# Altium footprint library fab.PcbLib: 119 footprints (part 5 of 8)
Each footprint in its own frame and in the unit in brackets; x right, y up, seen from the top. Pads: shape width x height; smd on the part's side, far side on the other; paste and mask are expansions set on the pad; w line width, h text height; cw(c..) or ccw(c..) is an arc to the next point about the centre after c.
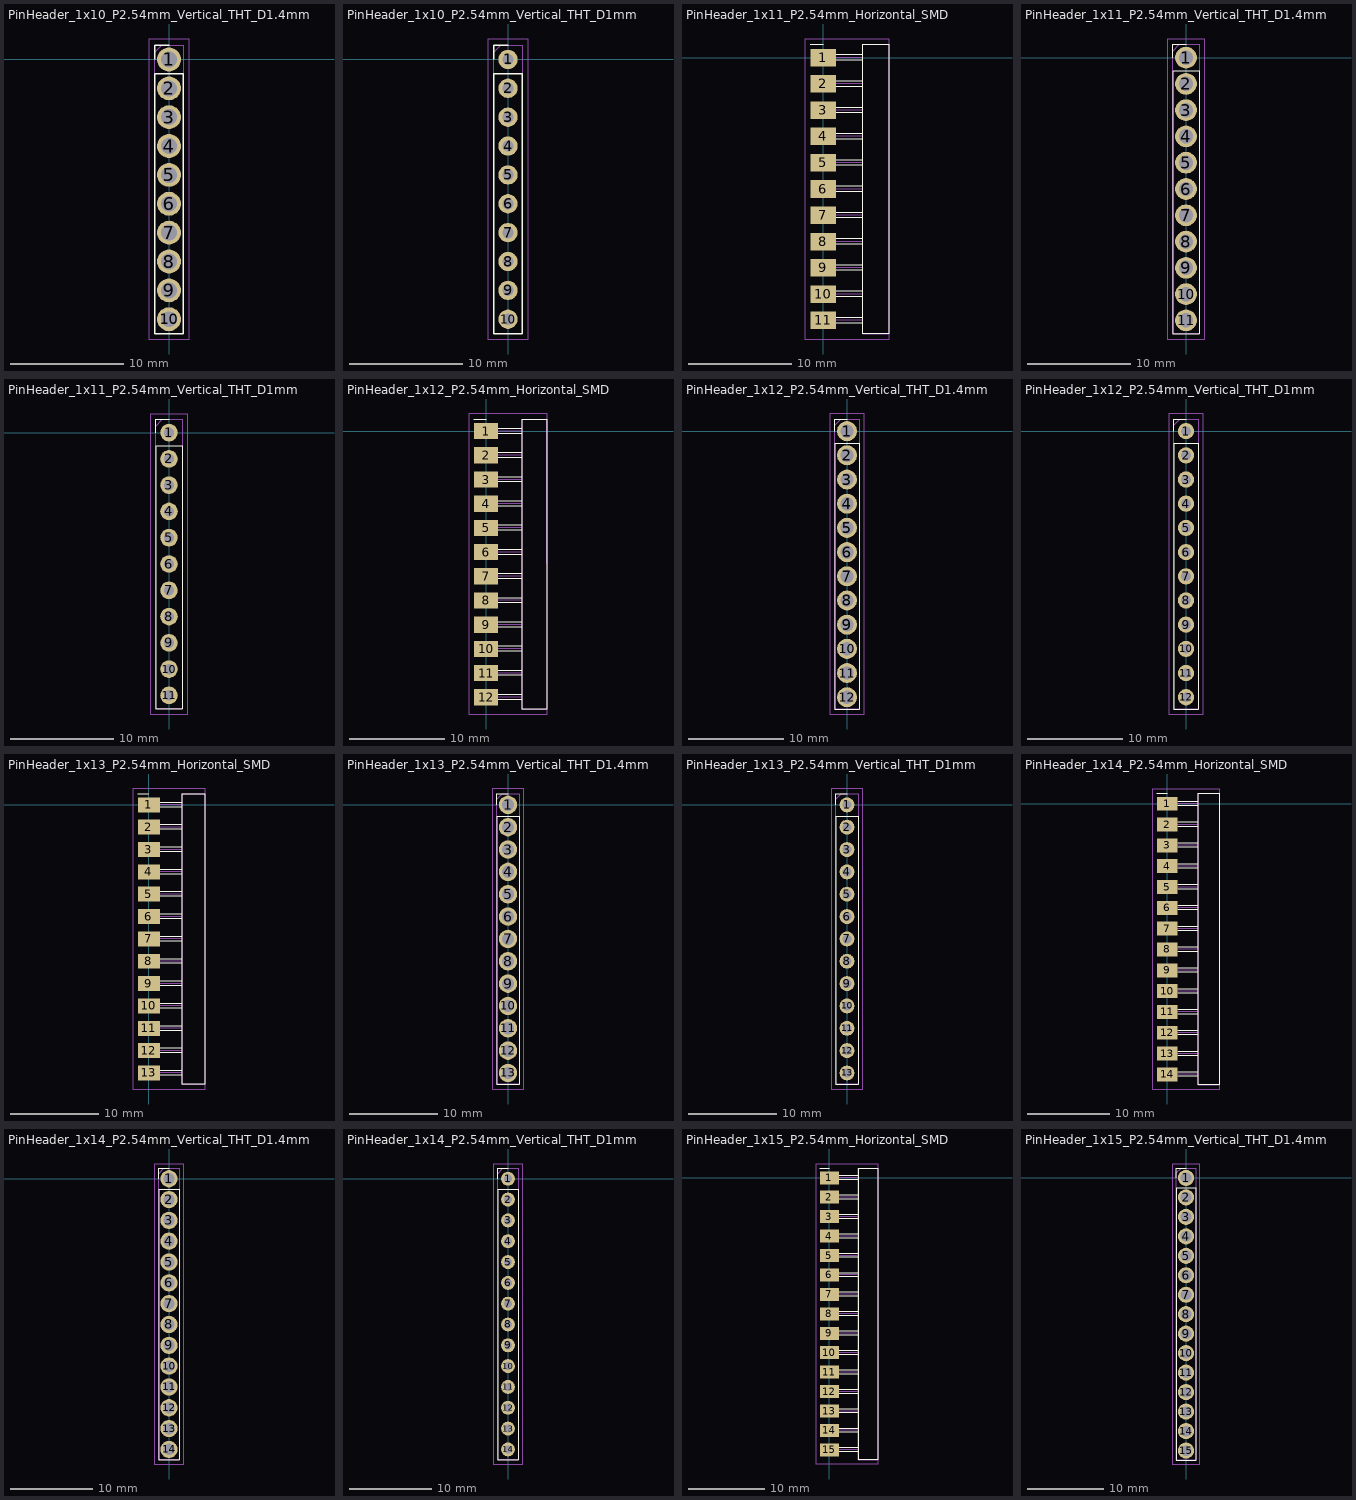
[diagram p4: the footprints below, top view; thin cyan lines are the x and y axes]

## PinHeader_1x10_P2.54mm_Vertical_THT_D1.4mm [mm]
pads (10):
  round 2.1 hole 1.4: 1(0,0) 2(0,-2.54) 3(0,-5.08) 4(0,-7.62) 5(0,-10.16) 6(0,-12.7) 7(0,-15.24) 8(0,-17.78) 9(0,-20.32) 10(0,-22.86)
F.SilkS:
  lines w0.12: -1.27,0 -1.27,1.27 0,1.27 ; -1.27,-24.13 -1.27,-1.27 1.27,-1.27 1.27,-24.13 -1.27,-24.13
F.CrtYd:
  lines w0.05: -1.8,-24.6 1.8,-24.6 1.8,1.8 -1.8,1.8 -1.8,-24.6
F.Fab:
  lines w0.1: -1.27,-24.13 -1.27,0.635 -0.635,1.27 1.27,1.27 1.27,-24.13 -1.27,-24.13
  text "%R" at 0.294,-9.283 h1

## PinHeader_1x10_P2.54mm_Vertical_THT_D1mm [mm]
pads (10):
  round 1.7 hole 1: 1(0,0)
  rrect100% 1.7x1.7 hole 1: 2(0,-2.54) 3(0,-5.08) 4(0,-7.62) 5(0,-10.16) 6(0,-12.7) 7(0,-15.24) 8(0,-17.78) 9(0,-20.32) 10(0,-22.86)
F.SilkS:
  lines w0.12: -1.27,0 -1.27,1.27 0,1.27 ; -1.27,-24.13 1.27,-24.13 1.27,-1.27 -1.27,-1.27 -1.27,-24.13
F.CrtYd:
  lines w0.05: -1.8,-24.6 -1.8,1.8 1.8,1.8 1.8,-24.6 -1.8,-24.6
F.Fab:
  lines w0.1: -1.27,-24.13 1.27,-24.13 1.27,1.27 -0.635,1.27 -1.27,0.635 -1.27,-24.13
  text "%R" at 0.294,-9.283 h1

## PinHeader_1x11_P2.54mm_Horizontal_SMD [mm]
pads (11):
  rect 2.5x1.7 smd: 1(0,0) 2(0,-2.54) 3(0,-5.08) 4(0,-7.62) 5(0,-10.16) 6(0,-12.7) 7(0,-15.24) 8(0,-17.78) 9(0,-20.32) 10(0,-22.86) 11(0,-25.4)
F.SilkS:
  lines w0.12: -1.27,1.27 0,1.27 ; 1.27,-25.654 3.81,-25.654 ; 1.27,-25.146 3.81,-25.146 ; 1.27,-23.114 3.81,-23.114 ; 1.27,-22.606 3.81,-22.606 ; 1.27,-20.574 3.81,-20.574 ; 1.27,-20.066 3.81,-20.066 ; 1.27,-18.034 3.81,-18.034 ; 1.27,-17.526 3.81,-17.526 ; 1.27,-15.494 3.81,-15.494 ; 1.27,-14.986 3.81,-14.986 ; 1.27,-12.954 3.81,-12.954 ; 1.27,-12.446 3.81,-12.446 ; 1.27,-10.414 3.81,-10.414 ; 1.27,-9.906 3.81,-9.906 ; 1.27,-7.874 3.81,-7.874 ; 1.27,-7.366 3.81,-7.366 ; 1.27,-5.334 3.81,-5.334 ; 1.27,-4.826 3.81,-4.826 ; 1.27,-2.794 3.81,-2.794 ; 1.27,-2.286 3.81,-2.286 ; 1.27,-0.254 3.81,-0.254 ; 1.27,0.254 3.81,0.254 ; 3.81,-26.67 3.81,1.27 6.35,1.27 6.35,-26.67 3.81,-26.67
F.CrtYd:
  lines w0.05: -1.8,-27.2 -1.8,1.8 6.4,1.8 6.4,-27.2 -1.8,-27.2
F.Fab:
  lines w0.1: -0.635,-25.4 3.81,-25.4 ; -0.635,-23.114 -0.635,-22.606 ; -0.635,-22.86 3.81,-22.86 ; -0.635,-20.574 -0.635,-20.066 ; -0.635,-20.32 3.81,-20.32 ; -0.635,-18.034 -0.635,-17.526 ; -0.635,-17.78 3.81,-17.78 ; -0.635,-15.494 -0.635,-14.986 ; -0.635,-15.24 3.81,-15.24 ; -0.635,-12.954 -0.635,-12.446 ; -0.635,-12.7 3.81,-12.7 ; -0.635,-10.414 -0.635,-9.906 ; -0.635,-10.16 3.81,-10.16 ; -0.635,-7.874 -0.635,-7.366 ; -0.635,-7.62 3.81,-7.62 ; -0.635,-5.334 -0.635,-4.826 ; -0.635,-5.08 3.81,-5.08 ; -0.635,-2.794 -0.635,-2.286 ; -0.635,-2.54 3.81,-2.54 ; -0.635,-0.254 -0.635,0.254 ; -0.635,0 3.81,0 ; 3.8,-26.67 6.35,-26.67 6.34,1.27 3.8,1.27 3.8,-26.67
  text "%R" at 2.834,-13.093 h1

## PinHeader_1x11_P2.54mm_Vertical_THT_D1.4mm [mm]
pads (11):
  round 2.1 hole 1.4: 1(0,0) 2(0,-2.54) 3(0,-5.08) 4(0,-7.62) 5(0,-10.16) 6(0,-12.7) 7(0,-15.24) 8(0,-17.78) 9(0,-20.32) 10(0,-22.86) 11(0,-25.4)
F.SilkS:
  lines w0.12: -1.27,0 -1.27,1.27 0,1.27 ; -1.27,-26.67 1.27,-26.67 1.27,-1.27 -1.27,-1.27 -1.27,-26.67
F.CrtYd:
  lines w0.05: -1.8,-27.2 -1.8,1.8 1.8,1.8 1.8,-27.2 -1.8,-27.2
F.Fab:
  lines w0.1: -1.27,-26.67 1.27,-26.67 1.27,1.27 -0.635,1.27 -1.27,0.635 -1.27,-26.67
  text "%R" at 0.294,-9.283 h1

## PinHeader_1x11_P2.54mm_Vertical_THT_D1mm [mm]
pads (11):
  round 1.7 hole 1: 1(0,0)
  rrect100% 1.7x1.7 hole 1: 2(0,-2.54) 3(0,-5.08) 4(0,-7.62) 5(0,-10.16) 6(0,-12.7) 7(0,-15.24) 8(0,-17.78) 9(0,-20.32) 10(0,-22.86) 11(0,-25.4)
F.SilkS:
  lines w0.12: -1.27,0 -1.27,1.27 0,1.27 ; -1.27,-26.67 -1.27,-1.27 1.27,-1.27 1.27,-26.67 -1.27,-26.67
F.CrtYd:
  lines w0.05: -1.8,-27.2 1.8,-27.2 1.8,1.8 -1.8,1.8 -1.8,-27.2
F.Fab:
  lines w0.1: -1.27,-26.67 -1.27,0.635 -0.635,1.27 1.27,1.27 1.27,-26.67 -1.27,-26.67
  text "%R" at 0.294,-9.283 h1

## PinHeader_1x12_P2.54mm_Horizontal_SMD [mm]
pads (12):
  rect 2.5x1.7 smd: 1(0,0) 2(0,-2.54) 3(0,-5.08) 4(0,-7.62) 5(0,-10.16) 6(0,-12.7) 7(0,-15.24) 8(0,-17.78) 9(0,-20.32) 10(0,-22.86) 11(0,-25.4) 12(0,-27.94)
F.SilkS:
  lines w0.12: -1.27,1.27 0,1.27 ; 1.27,-28.194 3.81,-28.194 ; 1.27,-27.686 3.81,-27.686 ; 1.27,-25.654 3.81,-25.654 ; 1.27,-25.146 3.81,-25.146 ; 1.27,-23.114 3.81,-23.114 ; 1.27,-22.606 3.81,-22.606 ; 1.27,-20.574 3.81,-20.574 ; 1.27,-20.066 3.81,-20.066 ; 1.27,-18.034 3.81,-18.034 ; 1.27,-17.526 3.81,-17.526 ; 1.27,-15.494 3.81,-15.494 ; 1.27,-14.986 3.81,-14.986 ; 1.27,-12.954 3.81,-12.954 ; 1.27,-12.446 3.81,-12.446 ; 1.27,-10.414 3.81,-10.414 ; 1.27,-9.906 3.81,-9.906 ; 1.27,-7.874 3.81,-7.874 ; 1.27,-7.366 3.81,-7.366 ; 1.27,-5.334 3.81,-5.334 ; 1.27,-4.826 3.81,-4.826 ; 1.27,-2.794 3.81,-2.794 ; 1.27,-2.286 3.81,-2.286 ; 1.27,-0.254 3.81,-0.254 ; 1.27,0.254 3.81,0.254 ; 3.81,-29.21 6.35,-29.21 6.35,1.27 3.81,1.27 3.81,-29.21
F.CrtYd:
  lines w0.05: -1.8,-29.7 6.4,-29.7 6.4,1.8 -1.8,1.8 -1.8,-29.7
F.Fab:
  lines w0.1: -0.635,-27.94 3.81,-27.94 ; -0.635,-25.4 3.81,-25.4 ; -0.635,-23.114 -0.635,-22.606 ; -0.635,-22.86 3.81,-22.86 ; -0.635,-20.574 -0.635,-20.066 ; -0.635,-20.32 3.81,-20.32 ; -0.635,-18.034 -0.635,-17.526 ; -0.635,-17.78 3.81,-17.78 ; -0.635,-15.494 -0.635,-14.986 ; -0.635,-15.24 3.81,-15.24 ; -0.635,-12.954 -0.635,-12.446 ; -0.635,-12.7 3.81,-12.7 ; -0.635,-10.414 -0.635,-9.906 ; -0.635,-10.16 3.81,-10.16 ; -0.635,-7.874 -0.635,-7.366 ; -0.635,-7.62 3.81,-7.62 ; -0.635,-5.334 -0.635,-4.826 ; -0.635,-5.08 3.81,-5.08 ; -0.635,-2.794 -0.635,-2.286 ; -0.635,-2.54 3.81,-2.54 ; -0.635,-0.254 -0.635,0.254 ; -0.635,0 3.81,0 ; 3.8,-29.21 6.35,-29.21 6.34,1.27 3.8,1.27 3.81,-29.21
  text "%R" at 2.834,-14.363 h1

## PinHeader_1x12_P2.54mm_Vertical_THT_D1.4mm [mm]
pads (12):
  round 2.1 hole 1.4: 1(0,0) 2(0,-2.54) 3(0,-5.08) 4(0,-7.62) 5(0,-10.16) 6(0,-12.7) 7(0,-15.24) 8(0,-17.78) 9(0,-20.32) 10(0,-22.86) 11(0,-25.4) 12(0,-27.94)
F.SilkS:
  lines w0.12: -1.27,0 -1.27,1.27 0,1.27 ; -1.27,-29.21 1.27,-29.21 1.27,-1.27 -1.27,-1.27 -1.27,-29.21
F.CrtYd:
  lines w0.05: -1.8,-29.7 -1.8,1.8 1.8,1.8 1.8,-29.7 -1.8,-29.7
F.Fab:
  lines w0.1: -1.27,-29.21 1.27,-29.21 1.27,1.27 -0.635,1.27 -1.27,0.635 -1.27,-29.21
  text "%R" at 0.294,-9.283 h1

## PinHeader_1x12_P2.54mm_Vertical_THT_D1mm [mm]
pads (12):
  round 1.7 hole 1: 1(0,0)
  rrect100% 1.7x1.7 hole 1: 2(0,-2.54) 3(0,-5.08) 4(0,-7.62) 5(0,-10.16) 6(0,-12.7) 7(0,-15.24) 8(0,-17.78) 9(0,-20.32) 10(0,-22.86) 11(0,-25.4) 12(0,-27.94)
F.SilkS:
  lines w0.12: -1.27,0 -1.27,1.27 0,1.27 ; -1.27,-29.21 -1.27,-1.27 1.27,-1.27 1.27,-29.21 -1.27,-29.21
F.CrtYd:
  lines w0.05: -1.8,-29.7 1.8,-29.7 1.8,1.8 -1.8,1.8 -1.8,-29.7
F.Fab:
  lines w0.1: -1.27,-29.21 -1.27,0.635 -0.635,1.27 1.27,1.27 1.27,-29.21 -1.27,-29.21
  text "%R" at 0.294,-9.283 h1

## PinHeader_1x13_P2.54mm_Horizontal_SMD [mm]
pads (13):
  rect 2.5x1.7 smd: 1(0,0) 2(0,-2.54) 3(0,-5.08) 4(0,-7.62) 5(0,-10.16) 6(0,-12.7) 7(0,-15.24) 8(0,-17.78) 9(0,-20.32) 10(0,-22.86) 11(0,-25.4) 12(0,-27.94) 13(0,-30.48)
F.SilkS:
  lines w0.12: -1.27,1.27 0,1.27 ; 1.27,-30.734 3.81,-30.734 ; 1.27,-30.226 3.81,-30.226 ; 1.27,-28.194 3.81,-28.194 ; 1.27,-27.686 3.81,-27.686 ; 1.27,-25.654 3.81,-25.654 ; 1.27,-25.146 3.81,-25.146 ; 1.27,-23.114 3.81,-23.114 ; 1.27,-22.606 3.81,-22.606 ; 1.27,-20.574 3.81,-20.574 ; 1.27,-20.066 3.81,-20.066 ; 1.27,-18.034 3.81,-18.034 ; 1.27,-17.526 3.81,-17.526 ; 1.27,-15.494 3.81,-15.494 ; 1.27,-14.986 3.81,-14.986 ; 1.27,-12.954 3.81,-12.954 ; 1.27,-12.446 3.81,-12.446 ; 1.27,-10.414 3.81,-10.414 ; 1.27,-9.906 3.81,-9.906 ; 1.27,-7.874 3.81,-7.874 ; 1.27,-7.366 3.81,-7.366 ; 1.27,-5.334 3.81,-5.334 ; 1.27,-4.826 3.81,-4.826 ; 1.27,-2.794 3.81,-2.794 ; 1.27,-2.286 3.81,-2.286 ; 1.27,-0.254 3.81,-0.254 ; 1.27,0.254 3.81,0.254 ; 3.81,-31.75 3.81,1.27 6.35,1.27 6.35,-31.75 3.81,-31.75
F.CrtYd:
  lines w0.05: -1.8,-32.3 -1.8,1.8 6.4,1.8 6.4,-32.3 -1.8,-32.3
F.Fab:
  lines w0.1: -0.635,-30.48 3.81,-30.48 ; -0.635,-27.94 3.81,-27.94 ; -0.635,-25.4 3.81,-25.4 ; -0.635,-23.114 -0.635,-22.606 ; -0.635,-22.86 3.81,-22.86 ; -0.635,-20.574 -0.635,-20.066 ; -0.635,-20.32 3.81,-20.32 ; -0.635,-18.034 -0.635,-17.526 ; -0.635,-17.78 3.81,-17.78 ; -0.635,-15.494 -0.635,-14.986 ; -0.635,-15.24 3.81,-15.24 ; -0.635,-12.954 -0.635,-12.446 ; -0.635,-12.7 3.81,-12.7 ; -0.635,-10.414 -0.635,-9.906 ; -0.635,-10.16 3.81,-10.16 ; -0.635,-7.874 -0.635,-7.366 ; -0.635,-7.62 3.81,-7.62 ; -0.635,-5.334 -0.635,-4.826 ; -0.635,-5.08 3.81,-5.08 ; -0.635,-2.794 -0.635,-2.286 ; -0.635,-2.54 3.81,-2.54 ; -0.635,-0.254 -0.635,0.254 ; -0.635,0 3.81,0 ; 3.8,-31.75 6.35,-31.75 6.34,1.27 3.8,1.27 3.8,-31.75
  text "%R" at 2.834,-15.633 h1

## PinHeader_1x13_P2.54mm_Vertical_THT_D1.4mm [mm]
pads (13):
  round 2.1 hole 1.4: 1(0,0) 2(0,-2.54) 3(0,-5.08) 4(0,-7.62) 5(0,-10.16) 6(0,-12.7) 7(0,-15.24) 8(0,-17.78) 9(0,-20.32) 10(0,-22.86) 11(0,-25.4) 12(0,-27.94) 13(0,-30.48)
F.SilkS:
  lines w0.12: -1.27,0 -1.27,1.27 0,1.27 ; -1.27,-31.75 1.27,-31.75 1.27,-1.27 -1.27,-1.27 -1.27,-31.75
F.CrtYd:
  lines w0.05: -1.8,-32.3 -1.8,1.8 1.8,1.8 1.8,-32.3 -1.8,-32.3
F.Fab:
  lines w0.1: -1.27,-31.75 1.27,-31.75 1.27,1.27 -0.635,1.27 -1.27,0.635 -1.27,-31.75
  text "%R" at 0.294,-9.283 h1

## PinHeader_1x13_P2.54mm_Vertical_THT_D1mm [mm]
pads (13):
  round 1.7 hole 1: 1(0,0)
  rrect100% 1.7x1.7 hole 1: 2(0,-2.54) 3(0,-5.08) 4(0,-7.62) 5(0,-10.16) 6(0,-12.7) 7(0,-15.24) 8(0,-17.78) 9(0,-20.32) 10(0,-22.86) 11(0,-25.4) 12(0,-27.94) 13(0,-30.48)
F.SilkS:
  lines w0.12: -1.27,0 -1.27,1.27 0,1.27 ; -1.27,-31.75 -1.27,-1.27 1.27,-1.27 1.27,-31.75 -1.27,-31.75
F.CrtYd:
  lines w0.05: -1.8,-32.3 1.8,-32.3 1.8,1.8 -1.8,1.8 -1.8,-32.3
F.Fab:
  lines w0.1: -1.27,-31.75 -1.27,0.635 -0.635,1.27 1.27,1.27 1.27,-31.75 -1.27,-31.75
  text "%R" at 0.294,-9.283 h1

## PinHeader_1x14_P2.54mm_Horizontal_SMD [mm]
pads (14):
  rect 2.5x1.7 smd: 1(0,0) 2(0,-2.54) 3(0,-5.08) 4(0,-7.62) 5(0,-10.16) 6(0,-12.7) 7(0,-15.24) 8(0,-17.78) 9(0,-20.32) 10(0,-22.86) 11(0,-25.4) 12(0,-27.94) 13(0,-30.48) 14(0,-33.02)
F.SilkS:
  lines w0.12: -1.27,1.27 0,1.27 ; 1.27,-33.274 3.81,-33.274 ; 1.27,-32.766 3.81,-32.766 ; 1.27,-30.734 3.81,-30.734 ; 1.27,-30.226 3.81,-30.226 ; 1.27,-28.194 3.81,-28.194 ; 1.27,-27.686 3.81,-27.686 ; 1.27,-25.654 3.81,-25.654 ; 1.27,-25.146 3.81,-25.146 ; 1.27,-23.114 3.81,-23.114 ; 1.27,-22.606 3.81,-22.606 ; 1.27,-20.574 3.81,-20.574 ; 1.27,-20.066 3.81,-20.066 ; 1.27,-18.034 3.81,-18.034 ; 1.27,-17.526 3.81,-17.526 ; 1.27,-15.494 3.81,-15.494 ; 1.27,-14.986 3.81,-14.986 ; 1.27,-12.954 3.81,-12.954 ; 1.27,-12.446 3.81,-12.446 ; 1.27,-10.414 3.81,-10.414 ; 1.27,-9.906 3.81,-9.906 ; 1.27,-7.874 3.81,-7.874 ; 1.27,-7.366 3.81,-7.366 ; 1.27,-5.334 3.81,-5.334 ; 1.27,-4.826 3.81,-4.826 ; 1.27,-2.794 3.81,-2.794 ; 1.27,-2.286 3.81,-2.286 ; 1.27,-0.254 3.81,-0.254 ; 1.27,0.254 3.81,0.254 ; 3.81,-34.29 3.81,1.27 6.35,1.27 6.35,-34.29 3.81,-34.29
F.CrtYd:
  lines w0.05: -1.8,-34.8 -1.8,1.8 6.4,1.8 6.4,-34.8 -1.8,-34.8
F.Fab:
  lines w0.1: -0.635,-33.02 3.81,-33.02 ; -0.635,-30.48 3.81,-30.48 ; -0.635,-27.94 3.81,-27.94 ; -0.635,-25.4 3.81,-25.4 ; -0.635,-23.114 -0.635,-22.606 ; -0.635,-22.86 3.81,-22.86 ; -0.635,-20.574 -0.635,-20.066 ; -0.635,-20.32 3.81,-20.32 ; -0.635,-18.034 -0.635,-17.526 ; -0.635,-17.78 3.81,-17.78 ; -0.635,-15.494 -0.635,-14.986 ; -0.635,-15.24 3.81,-15.24 ; -0.635,-12.954 -0.635,-12.446 ; -0.635,-12.7 3.81,-12.7 ; -0.635,-10.414 -0.635,-9.906 ; -0.635,-10.16 3.81,-10.16 ; -0.635,-7.874 -0.635,-7.366 ; -0.635,-7.62 3.81,-7.62 ; -0.635,-5.334 -0.635,-4.826 ; -0.635,-5.08 3.81,-5.08 ; -0.635,-2.794 -0.635,-2.286 ; -0.635,-2.54 3.81,-2.54 ; -0.635,-0.254 -0.635,0.254 ; -0.635,0 3.81,0 ; 3.8,-34.29 6.35,-34.29 6.34,1.27 3.8,1.27 3.8,-34.29
  text "%R" at 2.834,-16.903 h1

## PinHeader_1x14_P2.54mm_Vertical_THT_D1.4mm [mm]
pads (14):
  round 2.1 hole 1.4: 1(0,0) 2(0,-2.54) 3(0,-5.08) 4(0,-7.62) 5(0,-10.16) 6(0,-12.7) 7(0,-15.24) 8(0,-17.78) 9(0,-20.32) 10(0,-22.86) 11(0,-25.4) 12(0,-27.94) 13(0,-30.48) 14(0,-33.02)
F.SilkS:
  lines w0.12: -1.27,0 -1.27,1.27 0,1.27 ; -1.27,-34.29 1.27,-34.29 1.27,-1.27 -1.27,-1.27 -1.27,-34.29
F.CrtYd:
  lines w0.05: -1.8,-34.8 -1.8,1.8 1.8,1.8 1.8,-34.8 -1.8,-34.8
F.Fab:
  lines w0.1: -1.27,-34.29 1.27,-34.29 1.27,1.27 -0.635,1.27 -1.27,0.635 -1.27,-34.29
  text "%R" at 0.294,-9.283 h1

## PinHeader_1x14_P2.54mm_Vertical_THT_D1mm [mm]
pads (14):
  round 1.7 hole 1: 1(0,0)
  rrect100% 1.7x1.7 hole 1: 2(0,-2.54) 3(0,-5.08) 4(0,-7.62) 5(0,-10.16) 6(0,-12.7) 7(0,-15.24) 8(0,-17.78) 9(0,-20.32) 10(0,-22.86) 11(0,-25.4) 12(0,-27.94) 13(0,-30.48) 14(0,-33.02)
F.SilkS:
  lines w0.12: -1.27,0 -1.27,1.27 0,1.27 ; -1.27,-34.29 -1.27,-1.27 1.27,-1.27 1.27,-34.29 -1.27,-34.29
F.CrtYd:
  lines w0.05: -1.8,-34.8 1.8,-34.8 1.8,1.8 -1.8,1.8 -1.8,-34.8
F.Fab:
  lines w0.1: -1.27,-34.29 -1.27,0.635 -0.635,1.27 1.27,1.27 1.27,-34.29 -1.27,-34.29
  text "%R" at 0.294,-9.283 h1

## PinHeader_1x15_P2.54mm_Horizontal_SMD [mm]
pads (15):
  rect 2.5x1.7 smd: 1(0,0) 2(0,-2.54) 3(0,-5.08) 4(0,-7.62) 5(0,-10.16) 6(0,-12.7) 7(0,-15.24) 8(0,-17.78) 9(0,-20.32) 10(0,-22.86) 11(0,-25.4) 12(0,-27.94) 13(0,-30.48) 14(0,-33.02) 15(0,-35.56)
F.SilkS:
  lines w0.12: -1.27,1.27 0,1.27 ; 1.27,-35.814 3.81,-35.814 ; 1.27,-35.306 3.81,-35.306 ; 1.27,-33.274 3.81,-33.274 ; 1.27,-32.766 3.81,-32.766 ; 1.27,-30.734 3.81,-30.734 ; 1.27,-30.226 3.81,-30.226 ; 1.27,-28.194 3.81,-28.194 ; 1.27,-27.686 3.81,-27.686 ; 1.27,-25.654 3.81,-25.654 ; 1.27,-25.146 3.81,-25.146 ; 1.27,-23.114 3.81,-23.114 ; 1.27,-22.606 3.81,-22.606 ; 1.27,-20.574 3.81,-20.574 ; 1.27,-20.066 3.81,-20.066 ; 1.27,-18.034 3.81,-18.034 ; 1.27,-17.526 3.81,-17.526 ; 1.27,-15.494 3.81,-15.494 ; 1.27,-14.986 3.81,-14.986 ; 1.27,-12.954 3.81,-12.954 ; 1.27,-12.446 3.81,-12.446 ; 1.27,-10.414 3.81,-10.414 ; 1.27,-9.906 3.81,-9.906 ; 1.27,-7.874 3.81,-7.874 ; 1.27,-7.366 3.81,-7.366 ; 1.27,-5.334 3.81,-5.334 ; 1.27,-4.826 3.81,-4.826 ; 1.27,-2.794 3.81,-2.794 ; 1.27,-2.286 3.81,-2.286 ; 1.27,-0.254 3.81,-0.254 ; 1.27,0.254 3.81,0.254 ; 3.81,-36.83 3.81,1.27 6.35,1.27 6.35,-36.83 3.81,-36.83
F.CrtYd:
  lines w0.05: -1.8,-37.4 -1.8,1.8 6.4,1.8 6.4,-37.4 -1.8,-37.4
F.Fab:
  lines w0.1: -0.635,-35.56 3.81,-35.56 ; -0.635,-33.02 3.81,-33.02 ; -0.635,-30.48 3.81,-30.48 ; -0.635,-27.94 3.81,-27.94 ; -0.635,-25.4 3.81,-25.4 ; -0.635,-23.114 -0.635,-22.606 ; -0.635,-22.86 3.81,-22.86 ; -0.635,-20.574 -0.635,-20.066 ; -0.635,-20.32 3.81,-20.32 ; -0.635,-18.034 -0.635,-17.526 ; -0.635,-17.78 3.81,-17.78 ; -0.635,-15.494 -0.635,-14.986 ; -0.635,-15.24 3.81,-15.24 ; -0.635,-12.954 -0.635,-12.446 ; -0.635,-12.7 3.81,-12.7 ; -0.635,-10.414 -0.635,-9.906 ; -0.635,-10.16 3.81,-10.16 ; -0.635,-7.874 -0.635,-7.366 ; -0.635,-7.62 3.81,-7.62 ; -0.635,-5.334 -0.635,-4.826 ; -0.635,-5.08 3.81,-5.08 ; -0.635,-2.794 -0.635,-2.286 ; -0.635,-2.54 3.81,-2.54 ; -0.635,-0.254 -0.635,0.254 ; -0.635,0 3.81,0 ; 3.8,-36.83 6.35,-36.83 6.34,1.27 3.8,1.27 3.8,-36.83
  text "%R" at 2.834,-18.173 h1

## PinHeader_1x15_P2.54mm_Vertical_THT_D1.4mm [mm]
pads (15):
  round 2.1 hole 1.4: 1(0,0) 2(0,-2.54) 3(0,-5.08) 4(0,-7.62) 5(0,-10.16) 6(0,-12.7) 7(0,-15.24) 8(0,-17.78) 9(0,-20.32) 10(0,-22.86) 11(0,-25.4) 12(0,-27.94) 13(0,-30.48) 14(0,-33.02) 15(0,-35.56)
F.SilkS:
  lines w0.12: -1.27,0 -1.27,1.27 0,1.27 ; -1.27,-36.83 1.27,-36.83 1.27,-1.27 -1.27,-1.27 -1.27,-36.83
F.CrtYd:
  lines w0.05: -1.8,-37.3 -1.8,1.8 1.8,1.8 1.8,-37.3 -1.8,-37.3
F.Fab:
  lines w0.1: -1.27,-36.83 1.27,-36.83 1.27,1.27 -0.635,1.27 -1.27,0.635 -1.27,-36.83
  text "%R" at 0.294,-9.283 h1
